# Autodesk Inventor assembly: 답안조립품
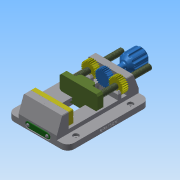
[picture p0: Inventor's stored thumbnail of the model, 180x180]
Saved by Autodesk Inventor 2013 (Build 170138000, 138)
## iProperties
Created: 2018-03
Part Number: 답안조립품
Document SubType Name: Assembly
Designer: Administrator
Mass: 1034.81 g
Surface Area: 918.51 cm^2
Volume: 340.422 cm^3
Density: 3.0398 g/cm^3
Author: Administrator
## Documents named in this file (10)
- C:\Users\Administrator\Desktop\380308V1015\답안조립품.iam
- C:\Users\Administrator\Desktop\380308V1015\바이스본체 A.ipt
- C:\Users\Administrator\Desktop\380308V1015\고정 플레이트.ipt
- C:\Users\Administrator\Desktop\380308V1015\바이스본체 B.ipt
- C:\Users\Administrator\Desktop\380308V1015\스퍼기어.ipt
- C:\Users\Administrator\Desktop\380308V1015\슬라이딩 부품.ipt
- C:\Users\Administrator\Desktop\380308V1015\십자오목머리나사 M3.ipt
- C:\Users\Administrator\Desktop\380308V1015\십자오목머리나사 M4.ipt
- C:\Users\Administrator\Desktop\380308V1015\지지대.ipt
- C:\Users\Administrator\Desktop\380308V1015\핸들.ipt
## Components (3 placed, 2 different names)
1. 고정 플레이트:1
2. 핸들:1 — 각도:1
3. 고정 플레이트:2
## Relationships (1: Angle 1)
- 각도:1 [Angle]: 핸들:1
